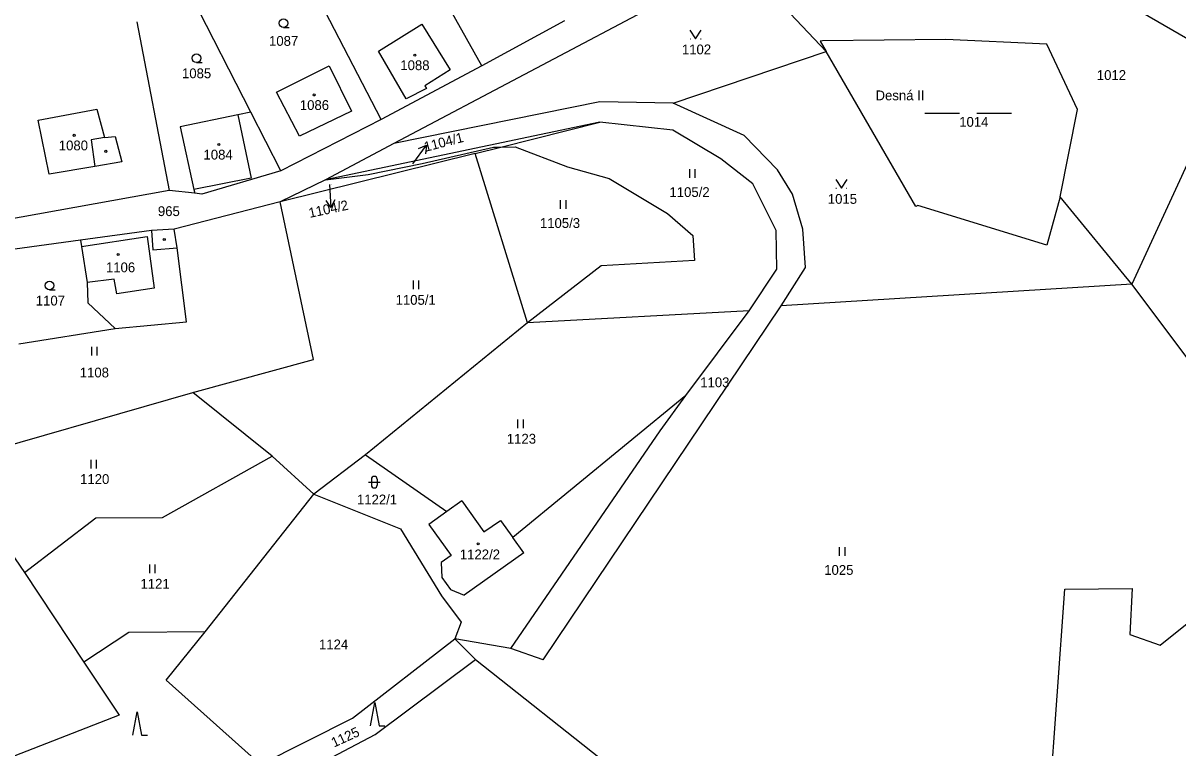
# Model space of a CAD drawing. Extents: x -670359 to -668019, y -978807 to -976674.
# Drawn here: x -669982.9 to -669783.1, y -977781.2 to -977655.6 of the extents above; entities that cross this region are included whole.
import ezdxf

# ---------------------------------------------------------------- set-up
doc = ezdxf.new("R2010")
doc.units = 0
for name, color, linetype in [('Hranice parcel', 7, 'Continuous'), ('Parcelní čísla', 7, 'Continuous'), ('Pop  PČ popisy', 7, 'Continuous'), ('Vnitřní kresba', 7, 'Continuous'), ('Značky budov', 7, 'Continuous'), ('Značky kultur', 7, 'Continuous')]:
    doc.layers.add(name, color=color, linetype=linetype)

msp = doc.modelspace()

# ---------------------------------------------------------------- linework, layer by layer
at = {"layer": 'Hranice parcel'}
for p, q in [((-669900.23, -977677.12), (-669883.11, -977672.77)), ((-669913.87, -977679.97), (-669901.49, -977677.14)), ((-669904.67, -977678.25), (-669900.23, -977677.12)), ((-669901.49, -977677.14), (-669900.23, -977677.12)), ((-669900.23, -977677.12), (-669897.75, -977677.09)), ((-669897.75, -977677.09), (-669888.73, -977680.55)), ((-669923.22, -977681.85), (-669913.87, -977679.97)), ((-669888.73, -977680.55), (-669881.48, -977682.58)), ((-669930.56, -977682.8), (-669923.22, -977681.85)), ((-669881.48, -977682.58), (-669871.4, -977688.59)), ((-669871.4, -977688.59), (-669867.03, -977692.44)), ((-669867.03, -977692.44), (-669866.71, -977696.78)), ((-669882.89, -977697.69), (-669895.63, -977707.53)), ((-669866.71, -977696.78), (-669882.89, -977697.69))]:
    msp.add_line(p, q, dxfattribs=at)
for points in [[(-669903.55, -977663.02), (-669919.14, -977635.11)], [(-669773.6, -977662.93), (-669808.82, -977642.52)], [(-669920.94, -977672.36), (-669936.3, -977642.69)], [(-669858.47, -977645.13), (-669843.94, -977660.55)], [(-669943.49, -977671.09), (-669953.69, -977651.05)], [(-669871.55, -977651.52), (-669918.75, -977676.5)], [(-669963.25, -977655.43), (-669957.62, -977684.64)], [(-669921.4, -977660.53), (-669913.91, -977655.85)], [(-669913.91, -977655.85), (-669908.99, -977663.73)], [(-669889.2, -977655.23), (-669903.55, -977663.02)], [(-669823.21, -977658.51), (-669844.56, -977658.72)], [(-669805.77, -977659.28), (-669823.21, -977658.51)], [(-669916.64, -977668.73), (-669921.4, -977660.53)], [(-669870.41, -977669.5), (-669843.94, -977660.55)], [(-669844.56, -977658.72), (-669844.96, -977658.8)], [(-669844.96, -977658.8), (-669843.94, -977660.55)], [(-669828.41, -977687.39), (-669843.94, -977660.55)], [(-669800.43, -977670.6), (-669805.77, -977659.28)], [(-669939.03, -977667.59), (-669929.94, -977663.06)], [(-669929.94, -977663.06), (-669926.06, -977670.87)], [(-669903.55, -977663.02), (-669920.94, -977672.36)], [(-669908.99, -977663.73), (-669913.37, -977666.48)], [(-669773.6, -977662.93), (-669791.07, -977700.83)], [(-669913.37, -977666.48), (-669913.13, -977666.96)], [(-669935.07, -977675.24), (-669939.03, -977667.59)], [(-669913.13, -977666.96), (-669916.64, -977668.73)], [(-669980.27, -977672.47), (-669970.13, -977670.57)], [(-669970.13, -977670.57), (-669968.82, -977675.44)], [(-669883.13, -977669.25), (-669918.75, -977676.5)], [(-669870.41, -977669.5), (-669883.13, -977669.25)], [(-669858.14, -977675.1), (-669870.41, -977669.5)], [(-669978.38, -977681.81), (-669980.27, -977672.47)], [(-669945.73, -977671.55), (-669955.72, -977673.6)], [(-669943.49, -977671.09), (-669945.73, -977671.55)], [(-669938.32, -977681.25), (-669943.49, -977671.09)], [(-669920.94, -977672.36), (-669938.32, -977681.25)], [(-669926.06, -977670.87), (-669935.07, -977675.24)], [(-669803.47, -977685.72), (-669800.43, -977670.6)], [(-669955.72, -977673.6), (-669953.34, -977684.46)], [(-669883.11, -977672.77), (-669930.56, -977682.8)], [(-669870.46, -977674.21), (-669883.11, -977672.77)], [(-669862.2, -977679.12), (-669870.46, -977674.21)], [(-669968.82, -977675.44), (-669966.98, -977675.27)], [(-669966.98, -977675.27), (-669965.84, -977679.66)], [(-669918.75, -977676.5), (-669930.56, -977682.8)], [(-669852.35, -977681.06), (-669858.14, -977675.1)], [(-669904.67, -977678.25), (-669938.45, -977686.61)], [(-669895.63, -977707.53), (-669904.67, -977678.25)], [(-669970.47, -977680.48), (-669978.38, -977681.81)], [(-669965.84, -977679.66), (-669970.47, -977680.48)], [(-669856.66, -977683.48), (-669862.2, -977679.12)], [(-669938.32, -977681.25), (-669951.97, -977685.25)], [(-669849.77, -977685.28), (-669852.35, -977681.06)], [(-669953.34, -977684.46), (-669953.19, -977685.12)], [(-669930.56, -977682.8), (-669938.45, -977686.61)], [(-669852.62, -977691.53), (-669856.66, -977683.48)], [(-669957.62, -977684.64), (-669986.76, -977689.88)], [(-669953.19, -977685.12), (-669957.62, -977684.64)], [(-669951.97, -977685.25), (-669953.19, -977685.12)], [(-669847.98, -977691.34), (-669849.77, -977685.28)], [(-669803.47, -977685.72), (-669805.74, -977694.12)], [(-669791.07, -977700.83), (-669803.47, -977685.72)], [(-669938.45, -977686.61), (-669956.78, -977691.35)], [(-669932.63, -977713.9), (-669938.45, -977686.61)], [(-669828.09, -977687.23), (-669828.41, -977687.39)], [(-669805.74, -977694.12), (-669828.09, -977687.23)], [(-669960.66, -977691.53), (-669972.97, -977693.24)], [(-669956.78, -977691.35), (-669960.66, -977691.53)], [(-669956.24, -977694.54), (-669956.78, -977691.35)], [(-669852.5, -977698.24), (-669852.62, -977691.53)], [(-669847.54, -977697.97), (-669847.98, -977691.34)], [(-669972.97, -977693.24), (-669985.99, -977695.04)], [(-669972.97, -977693.24), (-669972.8, -977694.32)], [(-669972.8, -977694.32), (-669971.8, -977700.55)], [(-669954.65, -977707.4), (-669956.24, -977694.54)], [(-669857.26, -977705.46), (-669852.5, -977698.24)], [(-669851.75, -977704.63), (-669847.54, -977697.97)], [(-669971.8, -977700.55), (-669971.71, -977704.06)], [(-669791.07, -977700.83), (-669851.75, -977704.63)], [(-669764.89, -977735.76), (-669791.07, -977700.83)], [(-669971.71, -977704.06), (-669966.96, -977708.51)], [(-669857.26, -977705.46), (-669895.63, -977707.53)], [(-669892.92, -977765.93), (-669851.75, -977704.63)], [(-669868.22, -977720.15), (-669857.26, -977705.46)], [(-669983.66, -977711.17), (-669966.96, -977708.51)], [(-669966.96, -977708.51), (-669954.65, -977707.4)], [(-669895.63, -977707.53), (-669923.66, -977730.39)], [(-669953.55, -977719.62), (-669932.63, -977713.9)], [(-669996.13, -977731.83), (-669953.55, -977719.62)], [(-669939.81, -977730.65), (-669953.55, -977719.62)], [(-669868.22, -977720.15), (-669898.16, -977744.72)], [(-669872.66, -977726.25), (-669868.22, -977720.15)], [(-669898.53, -977763.96), (-669872.66, -977726.25)], [(-669923.66, -977730.39), (-669932.58, -977737.23)], [(-669923.66, -977730.39), (-669909.56, -977740.23)], [(-669958.79, -977741.23), (-669939.81, -977730.65)], [(-669932.58, -977737.23), (-669939.81, -977730.65)], [(-669993.93, -977734.4), (-669982.65, -977750.8)], [(-669951.41, -977761.08), (-669932.58, -977737.23)], [(-669932.58, -977737.23), (-669917.59, -977743.22)], [(-669907, -977738.39), (-669909.56, -977740.23)], [(-669907, -977738.39), (-669903.19, -977743.73)], [(-669909.56, -977740.23), (-669912.68, -977742.47)], [(-669982.65, -977750.8), (-669970.31, -977741.3)], [(-669970.31, -977741.3), (-669958.79, -977741.23)], [(-669912.68, -977742.47), (-669908.84, -977747.84)], [(-669903.19, -977743.73), (-669900.27, -977741.75)], [(-669900.27, -977741.75), (-669898.16, -977744.72)], [(-669917.59, -977743.22), (-669910.49, -977754.84)], [(-669896.28, -977747.38), (-669898.16, -977744.72)], [(-669908.84, -977747.84), (-669910.58, -977749.07)], [(-669896.28, -977747.38), (-669906.58, -977754.71)], [(-669910.58, -977749.07), (-669910.44, -977751.63)], [(-669982.65, -977750.8), (-669972.41, -977766.32)], [(-669910.44, -977751.63), (-669908.93, -977753.75)], [(-669908.93, -977753.75), (-669906.58, -977754.71)], [(-669805.3, -977790.58), (-669802.62, -977753.64)], [(-669802.62, -977753.64), (-669791.02, -977753.57)], [(-669791.02, -977753.57), (-669791.38, -977761.49)], [(-669910.49, -977754.84), (-669907.11, -977759.38)], [(-669786.17, -977763.37), (-669775.42, -977754.76)], [(-669907.11, -977759.38), (-669908.21, -977762.26)], [(-669964.6, -977761.16), (-669972.41, -977766.32)], [(-669951.41, -977761.08), (-669964.6, -977761.16)], [(-669958.16, -977769.43), (-669951.41, -977761.08)], [(-669925.89, -977776.03), (-669908.21, -977762.26)], [(-669908.21, -977762.26), (-669904.6, -977765.84)], [(-669898.53, -977763.96), (-669908.21, -977762.26)], [(-669791.38, -977761.49), (-669786.17, -977763.37)], [(-669892.92, -977765.93), (-669898.53, -977763.96)], [(-669972.41, -977766.32), (-669966.28, -977775.47)], [(-669921.96, -977778.81), (-669904.6, -977765.84)], [(-669904.6, -977765.84), (-669881.63, -977784.08)], [(-669941.84, -977784.04), (-669958.16, -977769.43)], [(-669966.28, -977775.47), (-669994.9, -977786.6)], [(-669941.84, -977784.04), (-669925.89, -977776.03)], [(-669942.37, -977789.56), (-669921.96, -977778.81)]]:
    msp.add_lwpolyline(points, dxfattribs=at)
at = {"layer": 'Parcelní čísla'}
for p, q in [((-669914.49, -977677.37), (-669913.11, -977676.77)), ((-669928.97, -977686.27), (-669929.65, -977687.6))]:
    msp.add_line(p, q, dxfattribs=at)
for points in [[(-669915.49, -977679.99), (-669913.11, -977676.77), (-669913.28, -977678.26)], [(-669929.86, -977683.61), (-669929.65, -977687.6), (-669930.47, -977686.35)]]:
    msp.add_lwpolyline(points, dxfattribs=at)
at = {"layer": 'Vnitřní kresba'}
for points in [[(-669945.73, -977671.55), (-669943.43, -977682.48)], [(-669968.82, -977675.44), (-669971.14, -977675.85)], [(-669971.14, -977675.85), (-669970.47, -977680.48)], [(-669943.43, -977682.48), (-669953.34, -977684.46)], [(-669960.66, -977691.53), (-669960.48, -977694.89)], [(-669972.8, -977694.32), (-669961.45, -977692.58)], [(-669961.45, -977692.58), (-669960.2, -977701.52)], [(-669960.48, -977694.89), (-669956.24, -977694.54)], [(-669967.17, -977699.96), (-669971.8, -977700.55)], [(-669966.68, -977702.52), (-669967.17, -977699.96)], [(-669960.2, -977701.52), (-669966.68, -977702.52)]]:
    msp.add_lwpolyline(points, dxfattribs=at)
at = {"layer": 'Značky budov'}
for centre in [(-669915.13, -977661.19), (-669932.56, -977668.09), (-669974.07, -977675.08), (-669949.04, -977676.66), (-669966.45, -977695.72), (-669904.16, -977745.8)]:
    msp.add_circle(centre, 0.175, dxfattribs=at)
at = {"layer": 'Značky kultur'}
for p, q in [((-669937.85, -977656.4), (-669936.85, -977656.4)), ((-669867.5, -977658.35), (-669867.4, -977658.35)), ((-669865.7, -977658.35), (-669865.6, -977658.35)), ((-669952.91, -977662.49), (-669951.91, -977662.49)), ((-669826.87, -977671.22), (-669820.87, -977671.22)), ((-669817.87, -977671.22), (-669811.87, -977671.22)), ((-669867.62, -977680.91), (-669867.62, -977682.41)), ((-669866.62, -977682.41), (-669866.62, -977680.91)), ((-669842.25, -977684.24), (-669842.15, -977684.24)), ((-669840.45, -977684.24), (-669840.35, -977684.24)), ((-669889.95, -977686.3), (-669889.95, -977687.8)), ((-669888.95, -977687.8), (-669888.95, -977686.3)), ((-669915.41, -977700.22), (-669915.41, -977701.72)), ((-669914.41, -977701.72), (-669914.41, -977700.22)), ((-669978.35, -977701.85), (-669977.35, -977701.85)), ((-669971.09, -977711.73), (-669971.09, -977713.23)), ((-669970.09, -977713.23), (-669970.09, -977711.73)), ((-669897.34, -977724.27), (-669897.34, -977725.77)), ((-669896.34, -977725.77), (-669896.34, -977724.27)), ((-669971.18, -977731.25), (-669971.18, -977732.75)), ((-669970.18, -977732.75), (-669970.18, -977731.25)), ((-669923.13, -977735.13), (-669921.13, -977735.13)), ((-669922.63, -977734.63), (-669922.63, -977735.63)), ((-669921.63, -977734.63), (-669921.63, -977735.63)), ((-669841.67, -977746.38), (-669841.67, -977747.88)), ((-669840.67, -977747.88), (-669840.67, -977746.38)), ((-669961.05, -977749.38), (-669961.05, -977750.88)), ((-669960.05, -977750.88), (-669960.05, -977749.38))]:
    msp.add_line(p, q, dxfattribs=at)
for points in [[(-669867.55, -977656.85), (-669866.55, -977658.35), (-669865.55, -977656.85)], [(-669842.3, -977682.74), (-669841.3, -977684.24), (-669840.3, -977682.74)], [(-669922.79, -977777.32), (-669922.04, -977773.32), (-669921.29, -977777.32), (-669920.29, -977777.32)], [(-669963.89, -977778.92), (-669963.14, -977774.92), (-669962.39, -977778.92), (-669961.39, -977778.92)]]:
    msp.add_lwpolyline(points, dxfattribs=at)
for centre, radius in [((-669937.85, -977655.65), 0.75), ((-669952.91, -977661.74), 0.75), ((-669915.13, -977661.19), 0.175), ((-669932.56, -977668.09), 0.175), ((-669974.07, -977675.08), 0.175), ((-669949.04, -977676.66), 0.175), ((-669968.59, -977677.85), 0.175), ((-669958.47, -977693.12), 0.175), ((-669966.45, -977695.72), 0.175), ((-669978.35, -977701.1), 0.75), ((-669904.16, -977745.8), 0.175)]:
    msp.add_circle(centre, radius, dxfattribs=at)
for centre, start, end in [((-669922.13, -977734.63), 0, 180), ((-669922.13, -977735.63), 180, 0)]:
    msp.add_arc(centre, 0.5, start, end, dxfattribs=at)

# ---------------------------------------------------------------- texts
at = {"layer": 'Parcelní čísla'}
for s, height, p in [('1087', 1.7, (-669940.35, -977659.58)), ('1102', 1.7, (-669868.91, -977661.05)), ('1088', 1.7, (-669917.63, -977663.79)), ('1085', 1.7, (-669955.41, -977665.19)), ('1012', 1.7, (-669797.11, -977665.49)), ('1086', 1.7, (-669935.02, -977670.69)), ('1014', 1.7, (-669820.92, -977673.6)), ('1080', 1.7, (-669976.73, -977677.68)), ('1084', 1.7, (-669951.69, -977679.27)), ('1104/1', 0.1, (-669915.49, -977679.99)), ('1104/2', 0.1, (-669929.86, -977683.61)), ('1105/2', 1.7, (-669871.06, -977685.76)), ('1015', 1.7, (-669843.66, -977686.94)), ('965', 1.7, (-669959.58, -977689.06)), ('1105/3', 1.7, (-669893.48, -977691.12)), ('1106', 1.7, (-669968.57, -977698.79)), ('1107', 1.7, (-669980.71, -977704.55)), ('1105/1', 1.7, (-669918.45, -977704.42)), ('1108', 1.7, (-669973.1, -977717)), ('1103', 1.7, (-669865.74, -977718.7)), ('1123', 1.7, (-669899.2, -977728.47)), ('1120', 1.7, (-669973.04, -977735.45)), ('1122/1', 1.7, (-669925.14, -977738.99)), ('1122/2', 1.7, (-669907.33, -977748.5)), ('1025', 1.7, (-669844.28, -977751.19)), ('1121', 1.7, (-669962.59, -977753.58)), ('1124', 1.7, (-669931.71, -977764.09))]:
    msp.add_text(s, height=height, dxfattribs=at).set_placement(p)
for s, rotation, p in [('1104/1', 14.6209, (-669913.28, -977677.94)), ('1104/2', 12.0771, (-669933.3, -977689.38)), ('1125', 24.6051, (-669929.11, -977781.11))]:
    msp.add_text(s, height=1.7, rotation=rotation, dxfattribs=at).set_placement(p)
at = {"layer": 'Pop  PČ popisy'}
msp.add_text('Desná II', height=1.7, dxfattribs=at).set_placement((-669835.4, -977669.01))

doc.saveas('drawing.dxf')
